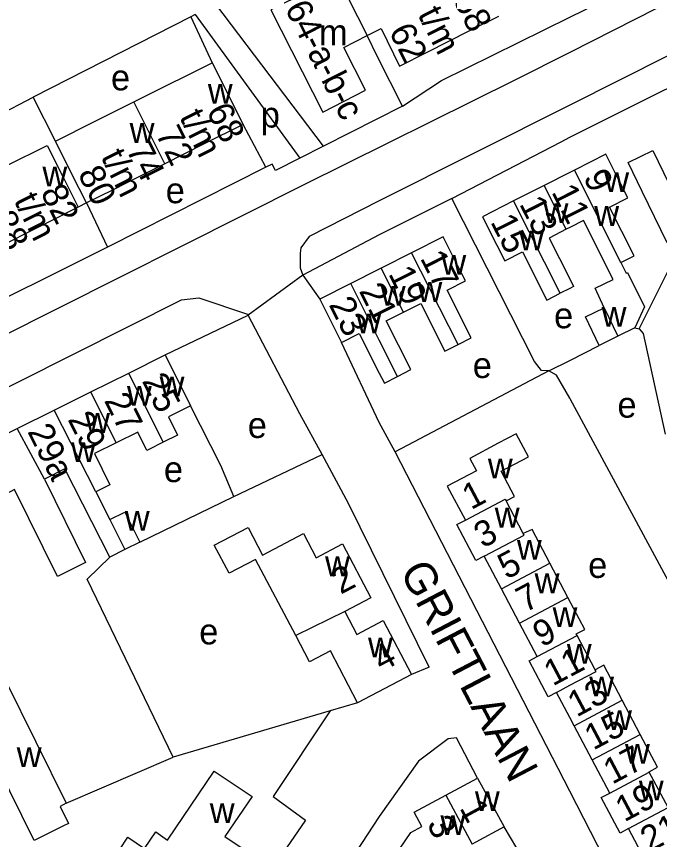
# Model space of a CAD drawing. Extents: x 156721 to 158827, y 386657 to 388950.
# Drawn here: x 157643.5 to 157743.6, y 387600.8 to 387728.9 of the extents above; entities that cross this region are included whole.
import ezdxf

# ---------------------------------------------------------------- set-up
doc = ezdxf.new("R2010")
doc.units = 0
for name, color, linetype in [('BLT_Basislijn', 7, 'Continuous'), ('BLT_Bebouwing', 7, 'Continuous'), ('BLT_Centroide', 7, 'Continuous'), ('BLT_Huisnummer', 7, 'Continuous'), ('BLT_Huisnummer_ tussenligend', 7, 'Continuous'), ('BLT_Huisnummer_reeks', 7, 'Continuous'), ('BLT_Onderverdeling_panden', 7, 'Continuous'), ('BLT_Straatnaam', 7, 'Continuous'), ('BLT_Vlakafsluiter', 7, 'Continuous')]:
    doc.layers.add(name, color=color, linetype=linetype)

msp = doc.modelspace()

# ---------------------------------------------------------------- linework, layer by layer
at = {"layer": 'BLT_Basislijn'}
for p, q in [((157755.89, 387736.64), (157729.65, 387723.33)), ((157671.34, 387729.23), (157670.67, 387728.88)), ((157671.34, 387729.23), (157687.65, 387706.86)), ((157670.67, 387728.88), (157646.13, 387716.35)), ((157670.67, 387728.88), (157673.98, 387721.71)), ((157729.65, 387723.33), (157721.09, 387718.98)), ((157721.09, 387718.98), (157688.24, 387702.69)), ((157620.45, 387703.08), (157646.13, 387716.35)), ((157649.59, 387709.51), (157646.13, 387716.35)), ((157682.35, 387705.48), (157678.79, 387712.1)), ((157691.34, 387708.72), (157687.65, 387706.86)), ((157682.35, 387705.48), (157657.68, 387693.04)), ((157688.24, 387702.69), (157582.23, 387649.51)), ((157654.4, 387699.9), (157653.11, 387699.23)), ((157654.4, 387699.9), (157657.68, 387693.04)), ((157688.08, 387688.68), (157690.72, 387684.9)), ((157666.66, 387676.24), (157679.6, 387682.43)), ((157726.4, 387673.78), (157729.65, 387675.4)), ((157726.4, 387673.78), (157702.45, 387661.16)), ((157729.65, 387608.36), (157702.45, 387661.16)), ((157677.38, 387654.2), (157691.09, 387660.73)), ((157707.75, 387627.66), (157705.01, 387626.5)), ((157696.62, 387622.1), (157692.37, 387620.85)), ((157692.37, 387620.85), (157667.89, 387613.67)), ((157736.7, 387594.67), (157729.65, 387608.36)), ((157728.65, 387587.52), (157719.42, 387602.79))]:
    msp.add_line(p, q, dxfattribs=at)
for points in [[(157729.65, 387728.79), (157745.7, 387736.7), (157758.6, 387740.51)], [(157691.34, 387708.72), (157667.4, 387740.35)], [(157703.63, 387714.98), (157709.7, 387718.95), (157729.65, 387728.79)], [(157761.67, 387726.47), (157761.36, 387727.29), (157759.58, 387728.03), (157756.17, 387728), (157752.65, 387726.67), (157729.65, 387715.11)], [(157729.65, 387710.11), (157759.48, 387725), (157761.29, 387725.95), (157761.67, 387726.47)], [(157703.63, 387714.98), (157699.74, 387722.64), (157698.13, 387725.93)], [(157729.65, 387715.11), (157700, 387700.2), (157689.08, 387694.65), (157687.8, 387692.89), (157687.66, 387692.07), (157687.69, 387689.78), (157688.08, 387688.68)], [(157703.63, 387714.98), (157691.34, 387708.72)], [(157711.29, 387700.59), (157728.3, 387709.43), (157729.65, 387710.11)], [(157687.65, 387706.86), (157683.83, 387704.94), (157683.3, 387705.94), (157682.35, 387705.48)], [(157711.29, 387700.59), (157700, 387694.92), (157688.08, 387688.68)], [(157726.4, 387673.78), (157725.24, 387673.82), (157724.18, 387675.23), (157711.29, 387700.59)], [(157740.46, 387680.33), (157746.82, 387693.06), (157769.43, 387698.32)], [(157657.68, 387693.04), (157633.19, 387680.84), (157631.84, 387680.17)], [(157569.88, 387629.94), (157567.78, 387633.84), (157669.19, 387684.81), (157671.93, 387685.15), (157679.51, 387682.6), (157679.6, 387682.43)], [(157691.09, 387660.73), (157687.64, 387667.07), (157679.6, 387682.43)], [(157739.79, 387680.47), (157740.46, 387680.33)], [(157740.46, 387680.33), (157741.07, 387679.6), (157744.52, 387663.89)], [(157702.45, 387661.16), (157700, 387665.74), (157694.13, 387678.17)], [(157729.65, 387675.4), (157734.25, 387677.7)], [(157729.65, 387669.54), (157727.59, 387673.11), (157726.4, 387673.78)], [(157752.39, 387629.76), (157751.64, 387630.02), (157748.62, 387634.41), (157729.71, 387669.43), (157729.65, 387669.54)], [(157677.38, 387654.2), (157675.35, 387659.05), (157670.61, 387668.31)], [(157707.75, 387627.66), (157695.21, 387653.13), (157691.09, 387660.73)], [(157662.71, 387647.13), (157677.38, 387654.2)], [(157667.89, 387613.67), (157654.53, 387641.35), (157658.04, 387644.79)], [(157692.37, 387620.85), (157683.49, 387607.52), (157688.52, 387603.84)], [(157715.3, 387610.4), (157712.01, 387616.64), (157710.73, 387616.48), (157706.1, 387613), (157700, 387604.4), (157663.66, 387548.92)], [(157651.26, 387606.47), (157667.89, 387613.67)], [(157688.52, 387603.84), (157652.49, 387551.43), (157640.05, 387558.25)]]:
    msp.add_lwpolyline(points, dxfattribs=at)
at = {"layer": 'BLT_Bebouwing'}
for p, q in [((157714.1, 387726.73), (157718.61, 387728.97)), ((157707.44, 387723.34), (157714.1, 387726.73)), ((157694.46, 387724.07), (157698.13, 387725.93)), ((157673.98, 387721.71), (157678.79, 387712.1)), ((157661.78, 387715.61), (157667.83, 387718.64)), ((157655.68, 387712.55), (157661.78, 387715.61)), ((157649.59, 387709.51), (157655.68, 387712.55)), ((157678.79, 387712.1), (157672.65, 387709.02)), ((157672.65, 387709.02), (157666.6, 387705.98)), ((157666.6, 387705.98), (157660.58, 387702.95)), ((157730.37, 387705), (157729.65, 387704.64)), ((157729.65, 387704.64), (157725.65, 387702.61)), ((157725.65, 387702.61), (157720.9, 387700.21)), ((157646.84, 387696.09), (157640.81, 387693.08)), ((157729.65, 387696.06), (157729.11, 387695.79)), ((157705.04, 387692.15), (157700.31, 387689.75)), ((157695.55, 387687.34), (157690.72, 387684.9)), ((157729.65, 387686.58), (157728.17, 387685.83)), ((157690.72, 387684.9), (157694.13, 387678.17)), ((157661, 387673.42), (157666.66, 387676.24)), ((157666.66, 387676.24), (157670.61, 387668.31)), ((157655.09, 387670.48), (157661, 387673.42)), ((157649.38, 387667.64), (157655.09, 387670.48)), ((157643.62, 387664.77), (157649.38, 387667.64)), ((157634.91, 387660.43), (157643.62, 387664.77)), ((157719.01, 387639.83), (157716.31, 387644.91)), ((157729.37, 387638.49), (157726.55, 387643.82)), ((157721.84, 387634.5), (157719.01, 387639.83)), ((157724.6, 387629.31), (157721.84, 387634.5)), ((157733.61, 387627.25), (157730.79, 387632.59)), ((157705.01, 387626.5), (157696.62, 387622.1)), ((157729.65, 387619.81), (157727.57, 387623.73)), ((157646.27, 387600.68), (157635.77, 387621.87)), ((157740.63, 387617.18), (157737.82, 387622.51)), ((157730.32, 387618.54), (157729.65, 387619.81)), ((157733.15, 387613.22), (157730.32, 387618.54)), ((157735.89, 387608.05), (157733.15, 387613.22)), ((157744.95, 387605.8), (157742.04, 387611.31)), ((157710.36, 387607.73), (157715.3, 387610.4)), ((157715.3, 387610.4), (157719.42, 387602.79)), ((157741.61, 387597.24), (157738.8, 387602.54))]:
    msp.add_line(p, q, dxfattribs=at)
for points in [[(157689.91, 387733.37), (157689.61, 387733.96), (157688.56, 387733.42), (157688.86, 387732.85), (157683.12, 387729.93), (157691.21, 387714.05), (157697.85, 387717.43), (157694.46, 387724.07)], [(157698.13, 387725.93), (157700, 387726.89), (157700.31, 387727.04), (157703.14, 387721.18)], [(157703.14, 387721.18), (157707.44, 387723.34)], [(157667.83, 387718.64), (157669.19, 387719.32), (157673.98, 387721.71)], [(157642.03, 387705.73), (157648.29, 387708.86), (157650.87, 387703.7), (157653.11, 387699.23)], [(157654.4, 387699.9), (157652.16, 387704.37), (157649.59, 387709.51)], [(157737.63, 387690.65), (157739.68, 387691.68), (157735.86, 387699.24), (157738.7, 387700.68), (157737.52, 387703.02), (157735.26, 387707.48), (157730.37, 387705)], [(157748.04, 387696.83), (157748.66, 387695.55), (157744.82, 387693.68), (157740.92, 387701.69), (157738.73, 387706.19), (157742.58, 387708.06), (157746.7, 387699.59)], [(157660.58, 387702.95), (157658.48, 387701.9), (157654.4, 387699.9)], [(157720.9, 387700.21), (157716.06, 387697.76), (157718.32, 387693.3), (157719.54, 387690.9), (157722.29, 387692.29), (157726.09, 387684.78), (157728.17, 387685.83)], [(157653.11, 387699.23), (157648.52, 387696.93), (157646.84, 387696.09)], [(157735.01, 387683.56), (157733.62, 387686.61), (157736.41, 387687.97), (157731.78, 387697.14), (157729.65, 387696.06)], [(157729.11, 387695.79), (157726.43, 387694.43), (157729.65, 387688.08)], [(157712.26, 387677.86), (157714.31, 387678.89), (157710.55, 387686.33), (157713.4, 387687.77), (157712.19, 387690.17), (157709.94, 387694.63), (157705.04, 387692.15)], [(157737.63, 387690.65), (157738.45, 387688.99), (157738.64, 387689.09), (157741.29, 387683.71), (157739.79, 387680.47)], [(157700.31, 387689.75), (157700, 387689.6), (157695.55, 387687.34)], [(157729.65, 387688.08), (157730.25, 387686.89), (157729.65, 387686.58)], [(157703.78, 387682.88), (157706.46, 387684.24), (157710.21, 387676.82), (157712.26, 387677.86)], [(157702.85, 387672.91), (157704.91, 387673.96), (157701.09, 387681.53), (157703.78, 387682.88)], [(157734.25, 387677.7), (157732.11, 387682.18), (157735.01, 387683.56)], [(157739.79, 387680.47), (157737.14, 387679.15)], [(157694.13, 387678.17), (157696.89, 387679.56), (157700, 387673.42), (157700.79, 387671.86), (157702.85, 387672.91)], [(157737.14, 387679.15), (157734.25, 387677.7)], [(157670.61, 387668.31), (157667.18, 387666.6), (157668.6, 387663.77), (157666.36, 387662.65)], [(157666.36, 387662.65), (157664.12, 387661.54), (157663.83, 387661.39), (157662.41, 387664.24), (157659.03, 387662.56)], [(157719.73, 387653.52), (157721.06, 387654.22), (157718.98, 387658.14), (157723.21, 387660.39), (157721.3, 387663.98), (157718.5, 387662.49), (157714.08, 387660.15), (157715.11, 387658.22), (157710.59, 387655.82), (157713.4, 387650.53)], [(157659.03, 387662.56), (157655.65, 387660.88), (157658.05, 387656.04), (157655.86, 387654.95)], [(157658.04, 387644.79), (157651.04, 387658.5), (157647.87, 387656.91)], [(157647.87, 387656.91), (157654.26, 387643.93), (157649.9, 387641.78), (157643.22, 387655.32), (157638.84, 387652.99)], [(157655.86, 387654.95), (157658.06, 387650.62)], [(157722.42, 387648.44), (157719.73, 387653.52)], [(157658.06, 387650.62), (157660.38, 387651.79), (157662.71, 387647.13)], [(157716.31, 387644.91), (157715.05, 387644.24), (157712.08, 387649.83), (157713.4, 387650.53)], [(157686.99, 387632.56), (157680.74, 387644.42), (157676.62, 387642.26), (157674.32, 387646.64), (157679.57, 387649.4), (157681.83, 387645.1), (157688.22, 387648.45), (157690.2, 387644.68), (157694.28, 387646.83), (157698.69, 387638.43), (157694.63, 387636.3)], [(157726.55, 387643.82), (157723.79, 387649.06), (157722.42, 387648.44)], [(157662.71, 387647.13), (157660.37, 387645.96)], [(157660.37, 387645.96), (157658.04, 387644.79)], [(157730.79, 387632.59), (157730.67, 387632.82), (157731.99, 387633.52), (157729.37, 387638.49)], [(157694.63, 387636.3), (157696.49, 387632.75), (157700.6, 387634.9), (157705.01, 387626.5)], [(157696.62, 387622.1), (157692.38, 387630.19), (157689.15, 387628.49), (157686.99, 387632.56)], [(157727.57, 387623.73), (157726.29, 387623.06), (157723.33, 387628.64), (157724.6, 387629.31)], [(157737.82, 387622.51), (157734.94, 387627.95), (157733.61, 387627.25)], [(157635.77, 387621.87), (157635.49, 387622.43), (157639.97, 387624.65), (157641.8, 387625.56), (157651.26, 387606.47)], [(157742.04, 387611.31), (157742.01, 387611.37), (157743.33, 387612.07), (157740.63, 387617.18)], [(157667.03, 387600.74), (157674.31, 387611.49), (157680.2, 387607.51), (157675.98, 387601.28), (157678.95, 387599.26), (157675.89, 387594.74)], [(157703.16, 387599.33), (157704.92, 387601.9), (157706.64, 387602.83), (157705.43, 387605.06), (157710.36, 387607.73)], [(157738.8, 387602.54), (157737.49, 387601.84), (157734.56, 387607.35), (157735.89, 387608.05)], [(157651.26, 387606.47), (157650.3, 387605.99), (157651.62, 387603.33), (157650.75, 387602.9), (157646.27, 387600.68)], [(157719.42, 387602.79), (157715.02, 387600.41), (157714.48, 387600.12)], [(157659.54, 387599.2), (157660.87, 387601.17), (157663.43, 387599.43), (157665.19, 387602.02), (157667.03, 387600.74)]]:
    msp.add_lwpolyline(points, dxfattribs=at)
at = {"layer": 'BLT_Onderverdeling_panden'}
for p, q in [((157693.48, 387735.17), (157698.13, 387725.93)), ((157666.6, 387705.98), (157661.78, 387715.61)), ((157737.63, 387690.65), (157730.37, 387705)), ((157729.11, 387695.79), (157725.65, 387702.61)), ((157728.17, 387685.83), (157720.9, 387700.21)), ((157712.26, 387677.86), (157705.04, 387692.15)), ((157703.78, 387682.88), (157700.31, 387689.75)), ((157735.01, 387683.56), (157737.14, 387679.15)), ((157666.36, 387662.65), (157661, 387673.42)), ((157659.03, 387662.56), (157655.09, 387670.48)), ((157655.86, 387654.95), (157649.38, 387667.64)), ((157647.87, 387656.91), (157643.62, 387664.77)), ((157658.06, 387650.62), (157660.37, 387645.96)), ((157719.01, 387639.83), (157726.55, 387643.82)), ((157721.84, 387634.5), (157729.37, 387638.49)), ((157694.63, 387636.3), (157686.99, 387632.56)), ((157724.6, 387629.31), (157730.79, 387632.59)), ((157727.57, 387623.73), (157729.65, 387624.84)), ((157730.32, 387618.54), (157737.82, 387622.51)), ((157733.15, 387613.22), (157740.63, 387617.18)), ((157735.89, 387608.05), (157742.04, 387611.31)), ((157710.36, 387607.73), (157714.48, 387600.12)), ((157738.8, 387602.54), (157744.95, 387605.8))]:
    msp.add_line(p, q, dxfattribs=at)
for points in [[(157702.85, 387672.91), (157700, 387678.54), (157695.55, 387687.34)], [(157713.4, 387650.53), (157719.59, 387653.78), (157719.73, 387653.52)], [(157716.31, 387644.91), (157722.54, 387648.21), (157722.42, 387648.44)], [(157729.65, 387624.84), (157733.75, 387627), (157733.61, 387627.25)]]:
    msp.add_lwpolyline(points, dxfattribs=at)
at = {"layer": 'BLT_Vlakafsluiter'}
msp.add_line((157688.08, 387688.68), (157679.6, 387682.43), dxfattribs=at)

# ---------------------------------------------------------------- texts
at = {"layer": 'BLT_Centroide'}
for s, p in [('m', (157690.62, 387724.45)), ('e', (157658.23, 387717.42)), ('w', (157673.31, 387715.36)), ('p', (157681.55, 387711.63)), ('w', (157661.14, 387709.25)), ('w', (157647.56, 387702.48)), ('w', (157735.03, 387701.58)), ('e', (157666.75, 387699.85)), ('w', (157725.58, 387696.77)), ('w', (157733.47, 387696.33)), ('w', (157721.77, 387692.5)), ('w', (157709.67, 387688.73)), ('w', (157700.23, 387683.89)), ('w', (157705.94, 387684.5)), ('e', (157727.21, 387680.39)), ('w', (157734.62, 387680.62)), ('w', (157696.43, 387679.59)), ('e', (157714.55, 387672.65)), ('w', (157665.8, 387669.78)), ('w', (157660.72, 387668.34)), ('e', (157737.08, 387666.48)), ('w', (157654.2, 387664.11)), ('e', (157679.53, 387663.32)), ('w', (157652, 387659.58)), ('w', (157716.91, 387657.02)), ('e', (157666.47, 387656.45)), ('w', (157717.98, 387649.38)), ('w', (157660.39, 387648.88)), ('w', (157721.43, 387644.38)), ('w', (157691.56, 387641.81)), ('e', (157732.52, 387641.54)), ('w', (157724.19, 387639.16)), ('w', (157726.98, 387633.91)), ('e', (157671.97, 387631.2)), ('w', (157698.24, 387629.19)), ('w', (157729.2, 387628.19)), ('w', (157732.69, 387623.12)), ('w', (157735.48, 387617.88)), ('w', (157643.56, 387612.09)), ('w', (157738.26, 387612.62)), ('w', (157740.41, 387606.94)), ('w', (157714.89, 387605.27)), ('w', (157673.61, 387603.38)), ('w', (157709.52, 387601.53))]:
    msp.add_text(s, height=4, dxfattribs=at).set_placement(p)
at = {"layer": 'BLT_Huisnummer'}
for s, rotation, p in [('9', 296.8565, (157731.69, 387703.89)), ('15', 296.8469, (157717.24, 387696.98)), ('17', 296.8115, (157706.3, 387691.32)), ('23', 296.8674, (157692.08, 387684.08)), ('25', 296.4524, (157662.99, 387672.22)), ('29', 296.4627, (157651.44, 387666.24)), ('29a', 296.4604, (157645.16, 387664.34)), ('1', 27.9008, (157714.28, 387652.07)), ('5', 27.8986, (157719.82, 387641.24)), ('2', 27.6823, (157693.98, 387638.91)), ('9', 27.9055, (157725.28, 387630.68)), ('4', 27.6906, (157700.35, 387626.88)), ('13', 27.9034, (157730.71, 387619.8)), ('17', 27.9029, (157736.26, 387609.34)), ('1', 298.3891, (157712.43, 387605.74)), ('3', 298.3891, (157707.31, 387603.23)), ('21', 27.9795, (157742.02, 387598.76))]:
    msp.add_text(s, height=4, rotation=rotation, dxfattribs=at).set_placement(p)
at = {"layer": 'BLT_Huisnummer_ tussenligend'}
for s, rotation, p in [('11', 296.8565, (157726.75, 387701.61)), ('13', 296.8565, (157721.74, 387699.76)), ('19', 296.8115, (157701.35, 387688.91)), ('21', 296.8115, (157696.78, 387686.21)), ('27', 296.4524, (157657.1, 387669.17)), ('3', 27.9008, (157716.11, 387646.09)), ('7', 27.9008, (157722.69, 387636.08)), ('11', 27.9008, (157727.01, 387624.64)), ('15', 27.9008, (157733.32, 387614.66)), ('19', 27.9008, (157738.14, 387603.48))]:
    msp.add_text(s, height=4, rotation=rotation, dxfattribs=at).set_placement(p)
at = {"layer": 'BLT_Huisnummer_reeks'}
for s, rotation, p in [('58', 296.9805, (157711.46, 387731.45)), ('64-a-b-c', 296.9778, (157685.22, 387730.21)), ('t/m', 296.9805, (157705.91, 387729.27)), ('62', 296.9805, (157701.42, 387726.62)), ('68', 296.5746, (157673.01, 387714.23)), ('t/m', 296.5753, (157668.81, 387713.29)), ('72', 296.5222, (157665.1, 387710.68)), ('74', 296.5753, (157660.54, 387708.21)), ('t/m', 296.5753, (157656.58, 387707.1)), ('80', 296.5413, (157653, 387704.46)), ('82', 296.5746, (157647.2, 387701.57)), ('t/m', 296.5753, (157643.04, 387700.29)), ('88', 296.5484, (157639.4, 387697.47))]:
    msp.add_text(s, height=4, rotation=rotation, dxfattribs=at).set_placement(p)
at = {"layer": 'BLT_Straatnaam'}
msp.add_text('GRIFTLAAN', height=5, rotation=297.5919, dxfattribs=at).set_placement((157703.12, 387642.61))

doc.saveas('drawing.dxf')
